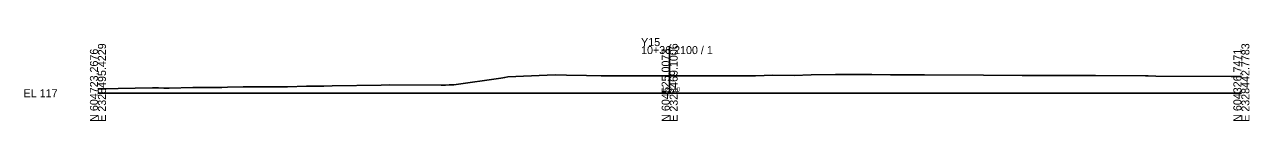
# Model space of a CAD drawing. Extents: x -26 to 2328584, y 1490 to 604564.
# Drawn here: x 1374.3 to 1802.8, y 1490.3 to 1519.3 of the extents above; entities that cross this region are included whole.
import ezdxf

# ---------------------------------------------------------------- set-up
doc = ezdxf.new("R2010")
doc.units = 0
for name, color, linetype in [('Exist CMT Pavement', 7, 'Continuous'), ('Exist Cross Section Cell', 7, 'Continuous'), ('Exist XS Center Line Elevation Label', 7, 'Continuous'), ('Exist XS Ground Line', 7, 'Continuous'), ('Prop XS Earthwork Shape', 7, 'Continuous'), ('Scratch_Level_1', 7, 'Continuous')]:
    doc.layers.add(name, color=color, linetype=linetype)

msp = doc.modelspace()

# ---------------------------------------------------------------- linework, layer by layer
at = {"layer": 'Exist CMT Pavement'}
for points in [[(1599.9, 1506.1), (1599.9, 1506.2), (1600, 1506.2), (1600, 1506.1)], [(1600, 1506.1), (1600, 1506.2), (1600.1, 1506.2), (1600.1, 1506.1)]]:
    msp.add_lwpolyline(points, dxfattribs=at)
at = {"layer": 'Exist Cross Section Cell'}
for p, q in [((1600, 1500), (1600, 1516.52)), ((1400, 1500), (1600, 1500)), ((1600, 1500), (1800, 1500))]:
    msp.add_line(p, q, dxfattribs=at)
at = {"layer": 'Exist XS Ground Line'}
msp.add_lwpolyline([(1400, 1501.52), (1402.88, 1501.55), (1407.08, 1501.62), (1412.97, 1501.72), (1419.03, 1501.86), (1421.15, 1501.89), (1423.06, 1501.76), (1424.89, 1501.79), (1433.15, 1501.99), (1433.8, 1501.99), (1438.69, 1502.01), (1443.36, 1502.04), (1445.28, 1502.11), (1450.76, 1502.21), (1452.94, 1502.26), (1461.58, 1502.22), (1466.36, 1502.26), (1473, 1502.43), (1477.58, 1502.46), (1479, 1502.53), (1481.96, 1502.58), (1499.09, 1502.83), (1502.12, 1502.92), (1520.09, 1502.85), (1520.97, 1502.85), (1521.64, 1502.86), (1522.84, 1502.89), (1524.53, 1502.9), (1540.93, 1505.31), (1542.29, 1505.55), (1543.44, 1505.72), (1557.1, 1506.39), (1560.14, 1506.49), (1563.87, 1506.37), (1570.89, 1506.18), (1575.99, 1506.15), (1600, 1506.1), (1604.59, 1506.09), (1605.45, 1506.08), (1630.08, 1506.15), (1636.08, 1506.31), (1643.61, 1506.27), (1649.5, 1506.44), (1657.98, 1506.54), (1660.96, 1506.54), (1670.68, 1506.53), (1677.29, 1506.49), (1682.32, 1506.41), (1689.12, 1506.41), (1709.77, 1506.3), (1723.31, 1506.27), (1739.81, 1506.23), (1742.42, 1506.22), (1749.02, 1506.18), (1766.51, 1506.05), (1767.42, 1506.05), (1770.06, 1506.04), (1796.42, 1505.92), (1800, 1505.91)], dxfattribs=at)
at = {"layer": 'Prop XS Earthwork Shape'}
for points in [[(1600, 1506.2), (1600, 1506.1), (1599.9, 1506.1), (1599.9, 1506.2)], [(1600, 1506.1), (1600.1, 1506.1), (1600.1, 1506.2), (1600, 1506.2)]]:
    msp.add_lwpolyline(points, close=True, dxfattribs=at)

# ---------------------------------------------------------------- texts
at = {"layer": 'Exist Cross Section Cell'}
for s, p in [('E 2328495.4229', (1402.8, 1490)), ('E 2328469.1006', (1602.8, 1490)), ('E 2328442.7783', (1802.8, 1490)), ('N 604723.2676', (1400, 1490)), ('N 604525.0073', (1600, 1490)), ('N 604326.7471', (1800, 1490))]:
    msp.add_text(s, height=2.8, rotation=90, dxfattribs=at).set_placement(p)
for s, p in [('Y15', (1590, 1516.52)), ('10+36.2100 / 1', (1590, 1513.72)), ('EL 117', (1374, 1498.6))]:
    msp.add_text(s, height=2.8, dxfattribs=at).set_placement(p)
at = {"layer": 'Exist XS Center Line Elevation Label'}
msp.add_text('123.10', height=1.5, dxfattribs=at).set_placement((1597.31, 1500.59))
at = {"layer": 'Scratch_Level_1'}
msp.add_text('123.10', height=0.2, dxfattribs=at).set_placement((1599.64, 1506))

doc.saveas('drawing.dxf')
